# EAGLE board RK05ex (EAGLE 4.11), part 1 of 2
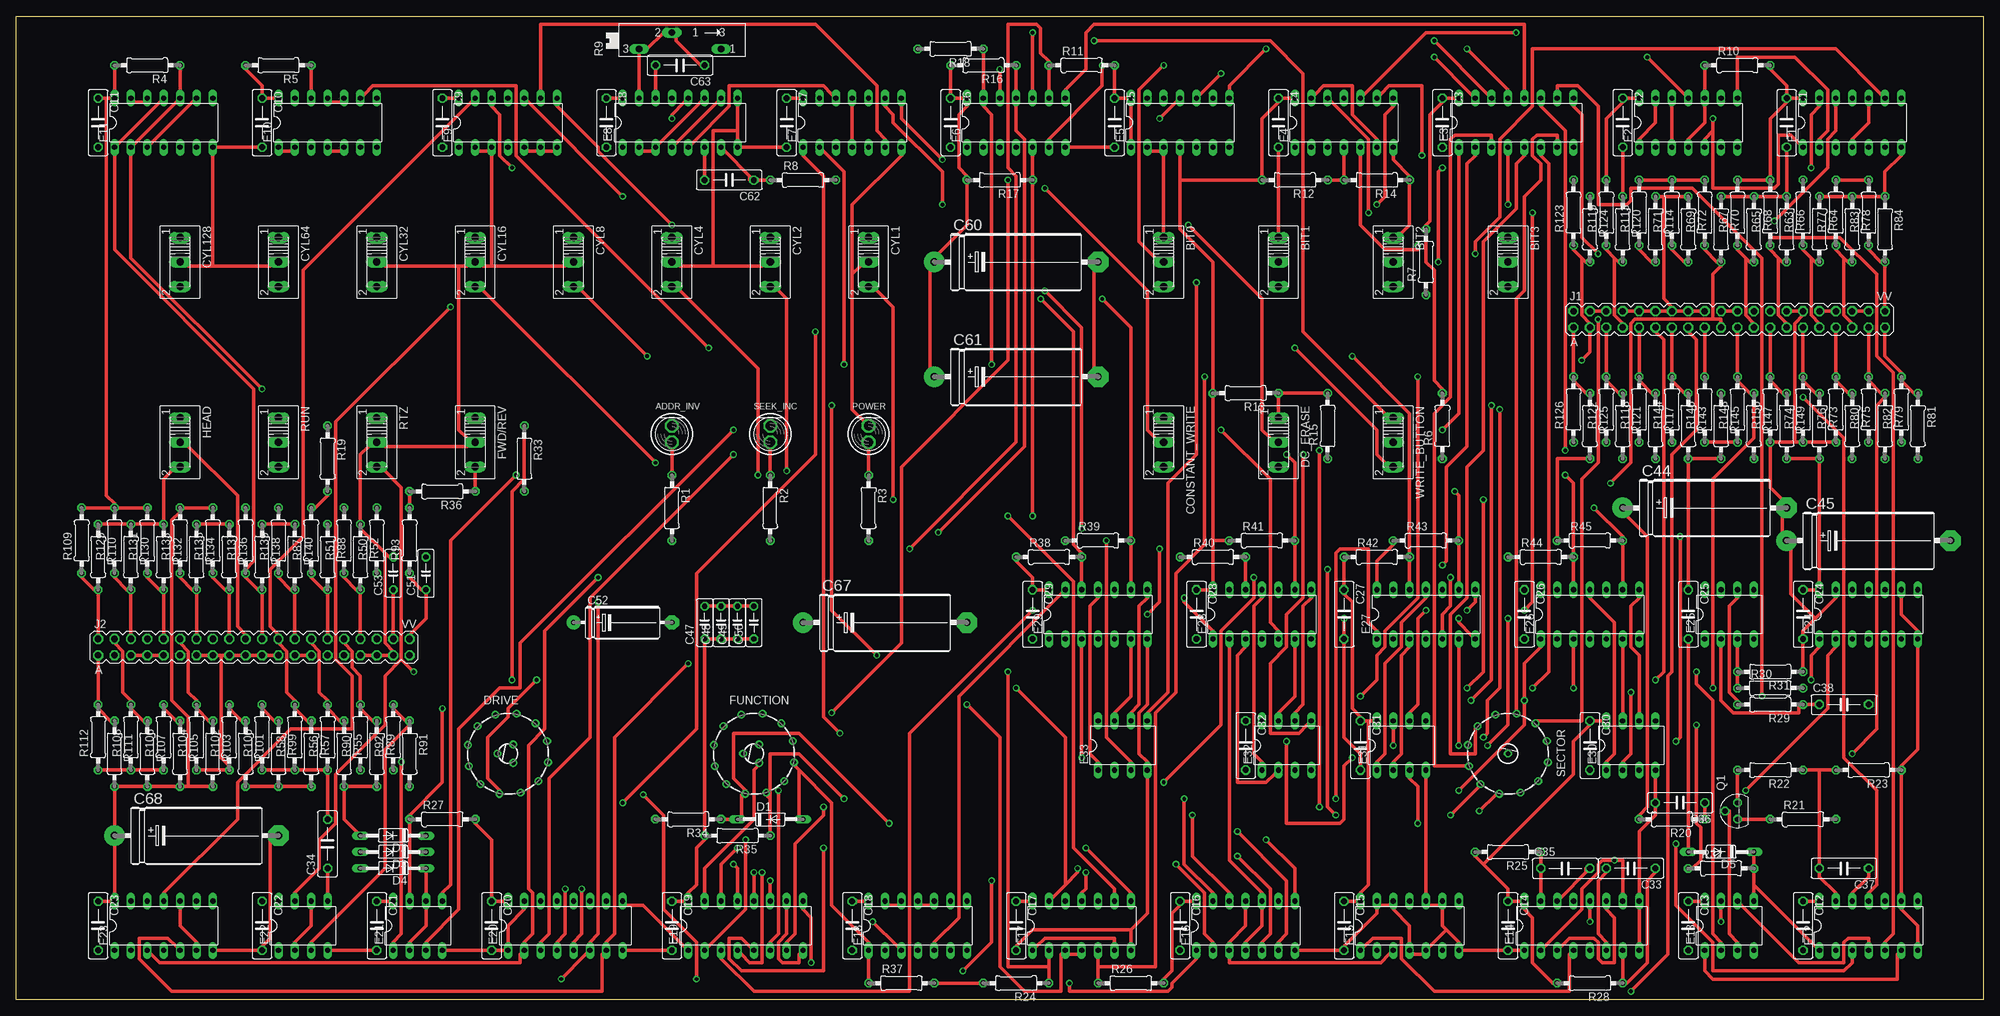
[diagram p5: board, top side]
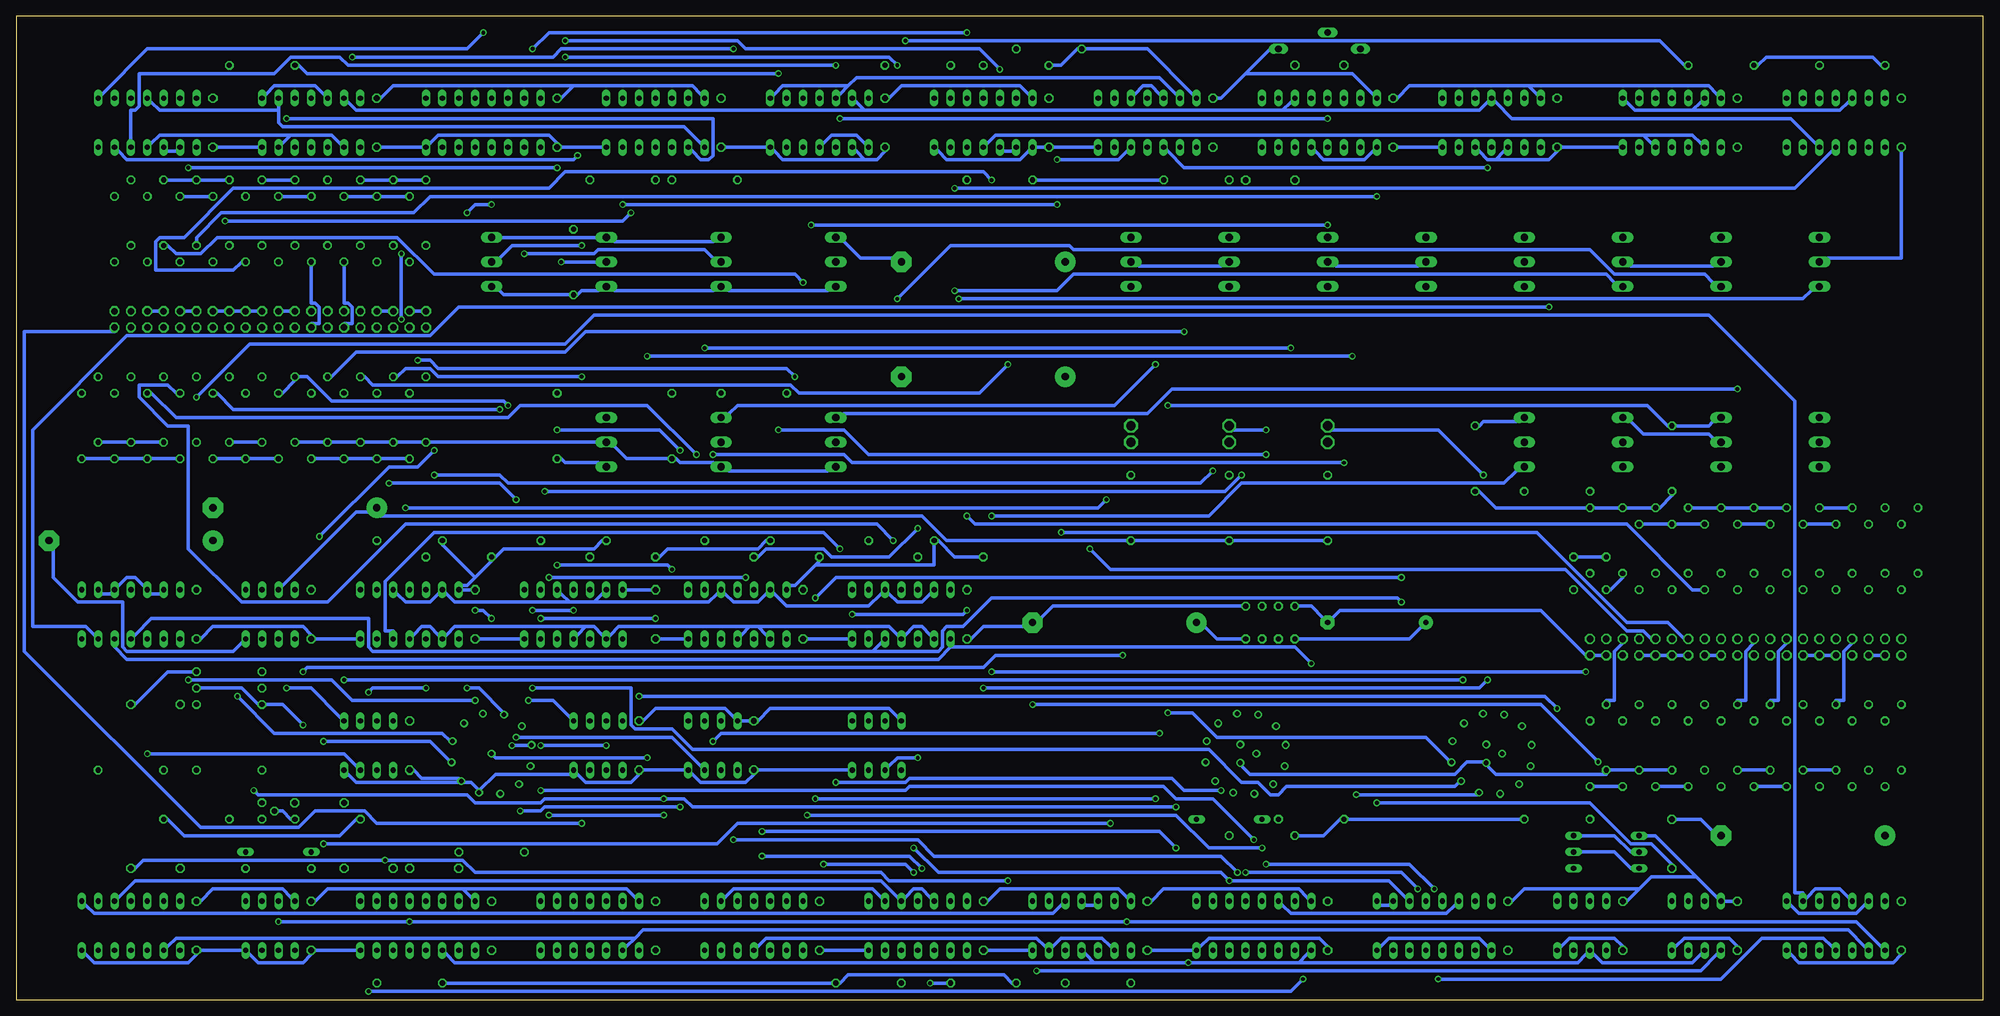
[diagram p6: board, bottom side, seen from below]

Size 304.8 x 152.4 mm. Coordinates in mm from the lower left corner, seen from the top.
Outline: 0,0 0,152.4 304.8,152.4 304.8,0 0,0
Copper layers (1*16): Top 0.035mm / dielectric 1.5mm / Bottom 0.035mm
Design rules "10mils": minimum track width 10mil, minimum drill 24mil, track to track 10mil, track to pad 10mil, pad to pad 10mil, via to via 10mil, smd to smd 10mil, copper to edge 25mil, drill to drill 10mil, minimum pad ring 10mil, minimum via ring 8mil, stop-mask expansion 0mil, vias tented up to drill 0mil, thermal gap 10mil
Net classes: 0 default: width 0.508 mm

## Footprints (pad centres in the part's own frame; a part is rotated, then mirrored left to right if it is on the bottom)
BULB = drill 1.422 octagon: A 0,0; B 0,2.54
255SB = drill 1.118 long: 1 -3.81,0; 2 0,0; 3 3.81,0
C075-032X103 = drill 0.914 octagon: 1 -3.81,0; 2 3.81,0
E25-9 = drill 1.118 pad 3.15 round: + -12.7,0 | drill 1.118 pad 3.15 octagon: - 12.7,0
C050-025X075 = drill 0.813 octagon: 1 -2.54,0; 2 2.54,0
E15-5 = drill 0.813 pad 2.159 round: + -7.62,0 | drill 0.813 pad 2.159 octagon: - 7.62,0
DO35-10 = drill 0.813 long: A 5.08,0; C -5.08,0
DO35Z10 = drill 0.813 long: A 5.08,0; C -5.08,0
50-3POLE30 = drill 0.7 pad 1.2 round: 1 6.207,-1.342; 2 4.704,-4.265; 3 1.941,-6.046; 4 -1.342,-6.207; 5 -4.265,-4.704; 6 -6.046,-1.941; 7 -6.207,1.342; 8 -4.704,4.265; 9 -1.941,6.046; 10 1.342,6.207; 11 4.265,4.704; 12 6.046,1.941; C1 0.825,-1.429; C2 -1.65,0; C3 0.825,1.429
DIL14 = drill 0.813 long: 1 -7.62,-3.81; 2 -5.08,-3.81; 3 -2.54,-3.81; 4 0,-3.81; 5 2.54,-3.81; 6 5.08,-3.81; 7 7.62,-3.81; 8 7.62,3.81; 9 5.08,3.81; 10 2.54,3.81; 11 0,3.81; 12 -2.54,3.81; 13 -5.08,3.81; 14 -7.62,3.81
DIL16 = drill 0.813 long: 1 -8.89,-3.81; 2 -6.35,-3.81; 3 -3.81,-3.81; 4 -1.27,-3.81; 5 1.27,-3.81; 6 3.81,-3.81; 7 6.35,-3.81; 8 8.89,-3.81; 9 8.89,3.81; 10 6.35,3.81; 11 3.81,3.81; 12 1.27,3.81; 13 -1.27,3.81; 14 -3.81,3.81; 15 -6.35,3.81; 16 -8.89,3.81
DIL08 = drill 0.813 long: 1 -3.81,-3.81; 2 -1.27,-3.81; 3 1.27,-3.81; 4 3.81,-3.81; 5 3.81,3.81; 6 1.27,3.81; 7 -1.27,3.81; 8 -3.81,3.81
DEC40PINV = drill 1.016 octagon: A -24.13,-1.27; AA 3.81,-1.27; B -24.13,1.27; BB 3.81,1.27; C -21.59,-1.27; CC 6.35,-1.27; D -21.59,1.27; DD 6.35,1.27; E -19.05,-1.27; EE 8.89,-1.27; F -19.05,1.27; FF 8.89,1.27; H -16.51,-1.27; HH 11.43,-1.27; J -16.51,1.27; JJ 11.43,1.27; K -13.97,-1.27; KK 13.97,-1.27; L -13.97,1.27; LL 13.97,1.27; M -11.43,-1.27; MM 16.51,-1.27; N -11.43,1.27; NN 16.51,1.27; P -8.89,-1.27; PP 19.05,-1.27; R -8.89,1.27; RR 19.05,1.27; S -6.35,-1.27; SS 21.59,-1.27; T -6.35,1.27; TT 21.59,1.27; U -3.81,-1.27; UU 24.13,-1.27; V -3.81,1.27; VV 24.13,1.27; W -1.27,-1.27; X -1.27,1.27; Y 1.27,-1.27; Z 1.27,1.27
TO92E = drill 0.813 octagon: B1 -1.27,0; B2 1.27,0; E 0,1.905
0207/10 = drill 0.813 octagon: 1 -5.08,0; 2 5.08,0
SP19L = drill 1.016 long: A 5.715,-1.27; E -6.985,-1.27; S -1.905,1.27
320-916 = drill 2.007 long: 1 0,4.013; 2 0,0; 3 0,-4.013
M9040P = drill 1.803 long: 1 0,4.699; 2 0,0; 3 0,-4.699
TL3XPO = drill 1.1 pad 1.422 long: 1 -2.54,0; 2 0,0; 3 2.54,0
50-1POLE30 = drill 0.7 pad 1.2 round: 1 6.207,-1.342; 2 4.704,-4.265; 3 1.941,-6.046; 4 -1.342,-6.207; 5 -4.265,-4.704; 6 -6.046,-1.941; 7 -6.207,1.342; 8 -4.704,4.265; 9 -1.941,6.046; 10 1.342,6.207; 11 4.265,4.704; 12 6.046,1.941; C 0,0

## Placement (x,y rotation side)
ADDR_INV  [BULB]  101.6,86.36 0 top
BIT0  [255SB]  177.8,114.3 270 top
BIT1  [255SB]  195.58,114.3 270 top
BIT2  [255SB]  213.36,114.3 270 top
BIT3  [255SB]  231.14,114.3 270 top
C1  .01uf  [C075-032X103]  274.32,135.89 270 top
C2  .01uf  [C075-032X103]  248.92,135.89 270 top
C3  .01uf  [C075-032X103]  220.98,135.89 270 top
C4  .01uf  [C075-032X103]  195.58,135.89 270 top
C5  .01uf  [C075-032X103]  170.18,135.89 270 top
C6  .01uf  [C075-032X103]  144.78,135.89 270 top
C7  .01uf  [C075-032X103]  119.38,135.89 270 top
C8  .01uf  [C075-032X103]  91.44,135.89 270 top
C9  .01uf  [C075-032X103]  66.04,135.89 270 top
C10  .01uf  [C075-032X103]  38.1,135.89 270 top
C11  .01uf  [C075-032X103]  12.7,135.89 270 top
C12  .01uf  [C075-032X103]  276.86,11.43 270 top
C13  .01uf  [C075-032X103]  259.08,11.43 270 top
C14  .01uf  [C075-032X103]  231.14,11.43 270 top
C15  .01uf  [C075-032X103]  205.74,11.43 270 top
C16  .01uf  [C075-032X103]  180.34,11.43 270 top
C17  .01uf  [C075-032X103]  154.94,11.43 270 top
C18  .01uf  [C075-032X103]  129.54,11.43 270 top
C19  .01uf  [C075-032X103]  101.6,11.43 270 top
C20  .01uf  [C075-032X103]  73.66,11.43 270 top
C21  .01uf  [C075-032X103]  55.88,11.43 270 top
C22  .01uf  [C075-032X103]  38.1,11.43 270 top
C23  .01uf  [C075-032X103]  12.7,11.43 270 top
C24  .01uf  [C075-032X103]  276.86,59.69 270 top
C25  .01uf  [C075-032X103]  259.08,59.69 270 top
C26  .01uf  [C075-032X103]  233.68,59.69 270 top
C27  .01uf  [C075-032X103]  205.74,59.69 270 top
C28  .01uf  [C075-032X103]  182.88,59.69 270 top
C29  .01uf  [C075-032X103]  157.48,59.69 270 top
C30  .01uf  [C075-032X103]  243.84,39.37 270 top
C31  .01uf  [C075-032X103]  208.28,39.37 270 top
C32  .01uf  [C075-032X103]  190.5,39.37 270 top
C33  470pf  [C075-032X103]  250.19,20.32 180 top
C34  .001uf  [C075-032X103]  48.26,24.13 90 top
C35  470pf  [C075-032X103]  240.03,20.32 0 top
C36  .033uf  [C075-032X103]  257.81,30.48 180 top
C37  .001uf  [C075-032X103]  283.21,20.32 180 top
C38  100pf  [C075-032X103]  283.21,45.72 0 top
C44  6.8uf  [E25-9]  261.62,76.2 0 top
C45  6.8uf  [E25-9]  287.02,71.12 0 top
C47  .22uf  [C050-025X075]  106.68,58.42 90 top
C48  .22uf  [C050-025X075]  109.22,58.42 90 top
C49  .22uf  [C050-025X075]  111.76,58.42 90 top
C50  .22uf  [C050-025X075]  114.3,58.42 90 top
C51  .001  [C050-025X075]  63.5,66.04 90 top
C52  39uf  [E15-5]  93.98,58.42 0 top
C53  .001  [C050-025X075]  58.42,66.04 90 top
C60  6.8uf  [E25-9]  154.94,114.3 0 top
C61  6.8uf  [E25-9]  154.94,96.52 0 top
C62  27pf  [C075-032X103]  110.49,127 180 top
C63  47pf  [C075-032X103]  102.87,144.78 180 top
C67  6.8uf  [E25-9]  134.62,58.42 0 top
C68  6.8uf  [E25-9]  27.94,25.4 0 top
CONSTANT_WRITE  [255SB]  177.8,86.36 270 top
CYL1  [255SB]  132.08,114.3 270 top
CYL2  [255SB]  116.84,114.3 270 top
CYL4  [255SB]  101.6,114.3 270 top
CYL8  [255SB]  86.36,114.3 270 top
CYL16  [255SB]  71.12,114.3 270 top
CYL32  [255SB]  55.88,114.3 270 top
CYL64  [255SB]  40.64,114.3 270 top
CYL128  [255SB]  25.4,114.3 270 top
D1  D664  [DO35-10]  116.84,27.94 0 top
D2  D664  [DO35-10]  58.42,25.4 180 top
D3  D664  [DO35-10]  58.42,22.86 180 top
D4  D664  [DO35-10]  58.42,20.32 180 top
D5  1N746  [DO35Z10]  264.16,22.86 180 top
DC_ERASE  [255SB]  195.58,86.36 270 top
DRIVE  50-3POLE30  [50-3POLE30]  76.2,38.1 0 top
E1  74LS10N  [DIL14]  284.48,135.89 0 top
E2  74LS74N  [DIL14]  259.08,135.89 0 top
E3  74LS42N  [DIL16]  232.41,135.89 0 top
E4  [DIL14]  205.74,135.89 0 top
E5  74LS74N  [DIL14]  180.34,135.89 0 top
E6  74LS04N  [DIL14]  154.94,135.89 0 top
E7  74LS00N  [DIL14]  129.54,135.89 0 top
E8  74LS123N  [DIL16]  102.87,135.89 0 top
E9  DS8881N  [DIL14]  76.2,135.89 0 top
E10  74LS00N  [DIL14]  48.26,135.89 0 top
E11  74LS74N  [DIL14]  22.86,135.89 0 top
E12  74LS04N  [DIL14]  287.02,11.43 0 top
E13  DS75451N  [DIL08]  265.43,11.43 0 top
E14  74HCT123N  [DIL16]  242.57,11.43 0 top
E15  74LS00N  [DIL14]  215.9,11.43 0 top
E16  74LS10N  [DIL14]  190.5,11.43 0 top
E17  74LS00N  [DIL14]  165.1,11.43 0 top
E18  74LS74N  [DIL14]  139.7,11.43 0 top
E19  74LS193N  [DIL16]  113.03,11.43 0 top
E20  74LS193N  [DIL16]  85.09,11.43 0 top
E21  DS75451N  [DIL08]  62.23,11.43 0 top
E22  DS75451N  [DIL08]  44.45,11.43 0 top
E23  74LS10N  [DIL14]  22.86,11.43 0 top
E24  74LS20N  [DIL14]  287.02,59.69 0 top
E25  LM741P  [DIL08]  265.43,59.69 0 top
E26  74LS00N  [DIL14]  243.84,59.69 0 top
E27  74LS00N  [DIL14]  218.44,59.69 0 top
E28  74LS00N  [DIL14]  193.04,59.69 0 top
E29  74LS00N  [DIL14]  167.64,59.69 0 top
E30  DS75451N  [DIL08]  250.19,39.37 0 top
E31  DS75451N  [DIL08]  214.63,39.37 0 top
E32  DS75451N  [DIL08]  196.85,39.37 0 top
E33  DS75451N  [DIL08]  171.45,39.37 0 top
FUNCTION  50-3POLE30  [50-3POLE30]  114.3,38.1 0 top
FWD/REV  [255SB]  71.12,86.36 270 top
HEAD  [255SB]  25.4,86.36 270 top
J1  DEC40PINSV  [DEC40PINV]  265.43,105.41 0 top
J2  DEC40PINSV  [DEC40PINV]  36.83,54.61 0 top
POWER  [BULB]  132.08,86.36 0 top
Q1  2N4894  [TO92E]  266.7,29.21 90 top
R1  0ohm  [0207/10]  101.6,76.2 270 top
R2  0ohm  [0207/10]  116.84,76.2 270 top
R3  0ohm  [0207/10]  132.08,76.2 270 top
R4  1K  [0207/10]  20.32,144.78 180 top
R5  56K  [0207/10]  40.64,144.78 180 top
R6  56K  [0207/10]  220.98,88.9 90 top
R7  1K  [0207/10]  218.44,114.3 90 top
R8  5.6k*  [0207/10]  121.92,127 0 top
R9  10K*  [SP19L]  103.5,148.59 0 top
R10  1K  [0207/10]  266.7,144.78 0 top
R11  1K  [0207/10]  165.1,144.78 0 top
R12  330  [0207/10]  198.12,127 180 top
R13  330  [0207/10]  190.5,93.98 180 top
R14  750  [0207/10]  210.82,127 180 top
R15  750  [0207/10]  203.2,88.9 90 top
R16  1K  [0207/10]  149.86,144.78 180 top
R17  1K  [0207/10]  152.4,127 180 top
R18  1K  [0207/10]  144.78,147.32 180 top
R19  1K  [0207/10]  48.26,83.82 270 top
R20  470K  [0207/10]  256.54,27.94 180 top
R21  330  [0207/10]  276.86,27.94 0 top
R22  120  [0207/10]  271.78,35.56 180 top
R23  68  [0207/10]  287.02,35.56 180 top
R24  1K  [0207/10]  154.94,2.54 180 top
R25  10K  [0207/10]  231.14,22.86 180 top
R26  1K  [0207/10]  172.72,2.54 0 top
R27  1K  [0207/10]  66.04,27.94 0 top
R28  22K  [0207/10]  243.84,2.54 180 top
R29  100K  [0207/10]  271.78,45.72 180 top
R30  100K  [0207/10]  271.78,48.26 0 top
R31  1M  [0207/10]  271.78,50.8 180 top
R32  1K  [0207/10]  264.16,20.32 0 top
R33  1K  [0207/10]  78.74,83.82 270 top
R34  1K  [0207/10]  104.14,27.94 180 top
R35  1K  [0207/10]  111.76,25.4 180 top
R36  1K  [0207/10]  66.04,78.74 180 top
R37  1K  [0207/10]  137.16,2.54 0 top
R38  1K  [0207/10]  160.02,68.58 0 top
R39  1K  [0207/10]  167.64,71.12 0 top
R40  1K  [0207/10]  185.42,68.58 0 top
R41  1K  [0207/10]  193.04,71.12 0 top
R42  1K  [0207/10]  210.82,68.58 0 top
R43  1K  [0207/10]  218.44,71.12 0 top
R44  1K  [0207/10]  236.22,68.58 0 top
R45  1K  [0207/10]  243.84,71.12 0 top
R50  120  [0207/10]  55.88,71.12 90 top
R51  120  [0207/10]  50.8,71.12 90 top
R52  120  [0207/10]  53.34,68.58 270 top
R55  120  [0207/10]  50.8,38.1 270 top
R56  120  [0207/10]  48.26,40.64 90 top
R57  120  [0207/10]  45.72,38.1 270 top
R58  120  [0207/10]  43.18,40.64 90 top
R63  120  [0207/10]  276.86,121.92 90 top
R64  120  [0207/10]  279.4,119.38 270 top
R65  120  [0207/10]  271.78,121.92 90 top
R66  120  [0207/10]  274.32,119.38 270 top
R67  120  [0207/10]  266.7,121.92 90 top
R68  120  [0207/10]  269.24,119.38 270 top
R69  120  [0207/10]  261.62,121.92 90 top
R70  120  [0207/10]  264.16,119.38 270 top
R71  120  [0207/10]  256.54,121.92 90 top
R72  120  [0207/10]  259.08,119.38 270 top
R73  120  [0207/10]  279.4,88.9 270 top
R74  120  [0207/10]  276.86,91.44 90 top
R75  120  [0207/10]  284.48,88.9 270 top
R76  120  [0207/10]  281.94,91.44 90 top
R77  120  [0207/10]  281.94,121.92 90 top
R78  120  [0207/10]  284.48,119.38 270 top
R79  120  [0207/10]  289.56,88.9 270 top
R80  120  [0207/10]  287.02,91.44 90 top
R81  120  [0207/10]  294.64,88.9 270 top
R82  120  [0207/10]  292.1,91.44 90 top
R83  120  [0207/10]  287.02,121.92 90 top
R84  120  [0207/10]  289.56,119.38 270 top
R87  120  [0207/10]  45.72,71.12 90 top
R88  120  [0207/10]  48.26,68.58 270 top
R89  120  [0207/10]  55.88,38.1 270 top
R90  120  [0207/10]  53.34,40.64 90 top
R91  120  [0207/10]  60.96,38.1 270 top
R92  120  [0207/10]  58.42,40.64 90 top
R93  120  [0207/10]  60.96,71.12 90 top
R99  120  [0207/10]  40.64,38.1 270 top
R100  120  [0207/10]  38.1,40.64 90 top
R101  120  [0207/10]  35.56,38.1 270 top
R102  120  [0207/10]  33.02,40.64 90 top
R103  120  [0207/10]  30.48,38.1 270 top
R104  120  [0207/10]  27.94,40.64 90 top
R105  120  [0207/10]  25.4,38.1 270 top
R106  120  [0207/10]  22.86,40.64 90 top
R107  120  [0207/10]  20.32,38.1 270 top
R108  120  [0207/10]  17.78,40.64 90 top
R109  120  [0207/10]  10.16,71.12 90 top
R110  120  [0207/10]  12.7,68.58 270 top
R111  120  [0207/10]  15.24,38.1 270 top
R112  120  [0207/10]  12.7,40.64 90 top
R113  120  [0207/10]  251.46,121.92 90 top
R114  120  [0207/10]  254,119.38 270 top
R117  120  [0207/10]  254,88.9 270 top
R118  120  [0207/10]  251.46,91.44 90 top
R119  120  [0207/10]  246.38,121.92 90 top
R120  120  [0207/10]  248.92,119.38 270 top
R121  120  [0207/10]  248.92,88.9 270 top
R122  120  [0207/10]  246.38,91.44 90 top
R123  120  [0207/10]  241.3,121.92 90 top
R124  120  [0207/10]  243.84,119.38 270 top
R125  120  [0207/10]  243.84,88.9 270 top
R126  120  [0207/10]  241.3,91.44 90 top
R129  120  [0207/10]  15.24,71.12 90 top
R130  120  [0207/10]  17.78,68.58 270 top
R131  120  [0207/10]  20.32,71.12 90 top
R132  120  [0207/10]  22.86,68.58 270 top
R133  120  [0207/10]  25.4,71.12 90 top
R134  120  [0207/10]  27.94,68.58 270 top
R135  120  [0207/10]  30.48,71.12 90 top
R136  120  [0207/10]  33.02,68.58 270 top
R137  120  [0207/10]  35.56,71.12 90 top
R138  120  [0207/10]  38.1,68.58 270 top
R139  120  [0207/10]  40.64,71.12 90 top
R140  120  [0207/10]  43.18,68.58 270 top
R143  120  [0207/10]  259.08,88.9 270 top
R144  120  [0207/10]  256.54,91.44 90 top
R145  120  [0207/10]  264.16,88.9 270 top
R146  120  [0207/10]  261.62,91.44 90 top
R147  120  [0207/10]  269.24,88.9 270 top
R148  120  [0207/10]  266.7,91.44 90 top
R149  120  [0207/10]  274.32,88.9 270 top
R150  120  [0207/10]  271.78,91.44 90 top
RTZ  [255SB]  55.88,86.36 270 top
RUN  [255SB]  40.64,86.36 270 top
S1  [320-916]  not placed on the board
S2  [M9040P]  not placed on the board
S3  TL32PO  [TL3XPO]  not placed on the board
S4  TL36PO  [TL3XPO]  not placed on the board
SECTOR  50-1POLE30  [50-1POLE30]  231.14,38.1 270 top
SEEK_INC  [BULB]  116.84,86.36 0 top
WRITE_BUTTON  MOM  [255SB]  213.36,86.36 270 top

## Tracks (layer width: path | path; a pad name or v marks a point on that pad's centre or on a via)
0BIT  (via drill 0.61)
  Top 0.508: v217.81,130.81 217.81,141.6 212.72,141.6 211.46,140.34 E4.9
  Bottom 0.508: v217.81,130.81 218.44,130.18 287.65,130.18 288.93,131.44 E1.6
1.44MHZ  (via drill 0.61)
  Top 0.508: v101.6,136.53 101.6,137.16 103.5,139.06 E8.12 | v177.16,136.53 179.71,139.06 E5.11
  Bottom 0.508: v177.16,136.53 v101.6,136.53
1BIT  (via drill 0.61)
  Top 0.508: v232.41,149.86 218.44,149.86 208.91,140.34 E4.10
  Bottom 0.508: v232.41,149.86 234.95,147.32 284.48,147.32 291.46,140.34 E1.8
1L  (via drill 0.61)
  Top 0.508: v252.73,146.05 258.44,140.34 E2.11 | v193.68,147.32 187.96,141.6 187.96,140.97 E5.8
  Bottom 0.508: 175.9,141.6 177.16,140.34 E5.12 | 175.9,141.6 174.62,142.88 127.64,142.88 125.09,140.34 E7.13 | 175.9,141.6 186.06,141.6 187.32,140.34 E5.8 | v252.73,146.05 221.62,146.05 220.34,147.32 v193.68,147.32
2.88MHZ
  Top 0.508: E8.4 102.23,132.72 108.58,139.06 E8.10
2BIT  (via drill 0.61)
  Top 0.508: v209.55,121.92 209.55,133.35 203.84,139.06 E4.12 | v272.42,120.65 280.67,128.91 280.67,133.35 281.94,134.62 281.94,138.43 E1.12
  Bottom 0.508: v209.55,121.92 210.82,120.65 v272.42,120.65
2H
  Bottom 0.508: 264.16,137.79 264.16,138.43 E2.9 | 264.16,137.79 264.16,135.89 263.52,135.25 201.29,135.25 198.75,132.72 E4.1 | 264.16,137.79 282.57,137.79 283.85,139.06 E1.11
2L
  Top 0.508: E2.3 256.54,133.35 256.54,138.43 E2.12 | E1.2 279.4,133.35 280.67,134.62 280.67,140.97 275.59,146.05 266.7,146.05 266.7,140.97 E2.8
  Bottom 0.508: E1.2 280.04,131.44 281.31,131.44 E1.3 | E2.8 266.06,140.34 264.8,141.6 258.44,141.6 257.18,140.34 E2.12
3BIT
  Top 0.508: E4.13 201.29,140.34 202.56,141.6 207.01,141.6 207.01,137.16 210.82,133.35 E4.6
4H  (via drill 0.61)
  Top 0.508: v262.89,136.53 262.89,134.62 | 262.89,134.62 261.62,133.35 E2.5 | 262.89,134.62 262.89,125.73 272.42,125.73 273.05,126.36 273.05,133.99 274.95,133.99 276.23,132.72 E1.1
  Bottom 0.508: v262.89,136.53 196.85,136.53 196.85,130.81 197.49,130.18 198.75,130.18 200.03,131.44 E4.2
4L
  Top 0.508: E1.4 284.48,133.35 287.02,135.89 287.02,138.43 E1.10
  Bottom 0.508: 262.25,133.99 255.91,133.99 254.63,132.72 E2.2 | 262.25,133.99 263.52,132.72 E2.6 | 262.25,133.99 282.57,133.99 283.85,132.72 E1.4
202_DETECT_L  (via drill 0.61)
  Top 0.508: v67.31,107.31 49.53,89.53 49.53,52.7 52.07,50.16 52.07,41.91 42.55,41.91 34.29,33.66 34.29,27.94 22.86,16.51 E23.11
  Bottom 0.508: v67.31,107.31 236.22,107.31 240.66,102.87 287.65,102.87 302.26,88.27 302.26,57.78 294,57.78 292.74,56.52 E24.6
+3V  (via drill 0.61)
  Top 0.508: E22.2 43.18,8.89 45.72,11.43 45.72,13.97 E22.6 | E21.2 60.96,8.89 63.5,11.43 63.5,13.97 E21.6 63.5,16.51 63.5,19.68 D4.C | E14.3 239.4,8.26 240.66,9.53 244.47,9.53 245.11,8.89 245.11,6.35 245.75,5.71 247.65,5.71 247.65,12.7 246.38,13.97 E14.11 | E19.1 103.5,8.26 97.16,14.61 94.61,14.61 E20.9 | v123.19,5.71 123.19,12.7 121.92,13.97 E19.9
  Bottom 0.508: E22.2 43.81,6.99 45.09,5.71 59.05,5.71 60.33,6.99 E21.2 61.59,6.99 62.87,5.71 106.05,5.71 | 137.79,5.71 139.06,6.99 E18.4 | 106.05,5.71 v123.19,5.71 137.79,5.71 | 106.05,5.71 104.78,6.99 E19.1 | E20.10 92.08,14.61 93.34,14.61 E20.9 | 137.79,5.71 236.85,5.71 238.12,6.99 E14.3
+3VA  (via drill 0.61)
  Top 0.508: v128.27,98.42 128.27,128.27 125.09,131.44 E7.2 | DC_ERASE.1 195.58,90.81 195.58,93.34 R13.1 196.22,93.98 202.56,93.98 R15.2
  Bottom 0.508: v128.27,98.42 134.62,92.08 193.04,92.08 194.31,90.81 DC_ERASE.1
+3VB
  Top 0.508: R12.1 203.84,127 205.1,127 R14.2 205.74,127.64 205.74,130.81 E4.4
+3VC  (via drill 0.61)
  Top 0.508: R4.1 25.4,144.15 25.4,140.97 E11.10 24.77,139.06 18.41,132.72 E11.2 17.78,130.81 17.78,114.94 v38.1,94.61
  Bottom 0.508: v38.1,94.61 125.73,94.61 129.54,90.81 176.53,90.81 CONSTANT_WRITE.1
+15V
  Top 0.508: R20.2 251.46,28.57 252.73,29.84 252.73,71.75 249.56,74.93 C44.+
  Bottom 0.508: R20.2 252.09,27.94 254.63,25.4 278.76,25.4 281.31,27.94 R21.2 | R1.2 102.23,71.12 116.2,71.12 R2.2 117.47,71.12 131.44,71.12 R3.2 132.72,71.12 160.66,71.12 164.47,74.93 248.28,74.93 C44.+ 250.19,75.56 252.09,75.56 263.52,64.14 E25.7
-15V
  Bottom 0.508: E25.4 269.88,55.24 271.14,53.98 287.65,53.98 288.29,54.61 288.29,61.59 295.27,61.59 299.08,65.41 299.08,69.85 C45.-
ADDR_COUNTER_1  (via drill 0.61)
  Top 0.508: v157.48,60.33 138.43,41.27 138.43,1.27 114.3,1.27 109.22,6.35 E19.3 | v175.26,59.69 177.16,61.59 v177.16,69.85
  Bottom 0.508: v157.48,60.33 158.12,59.69 v175.26,59.69 | v177.16,69.85 179.71,72.39 240.03,72.39 247.65,64.77 247.65,57.15 246.38,57.15 E26.5
ADDR_COUNTER_2  (via drill 0.61)
  Top 0.508: v113.03,24.77 113.03,13.97 107.31,8.26 E19.2 | v223.52,32.38 233.68,42.55 v233.68,46.35 233.68,52.07 236.22,54.61 E26.1 | v278.13,49.53 278.13,53.34 279.4,54.61 E24.1
  Bottom 0.508: v113.03,24.77 119.38,31.11 125.09,31.11 127,33.02 166.37,33.02 167,32.38 v223.52,32.38 | v278.13,49.53 255.91,49.53 252.73,46.35 v233.68,46.35
ADDR_COUNTER_4  (via drill 0.61)
  Top 0.508: v118.11,32.38 118.11,10.16 116.84,8.89 E19.6 | v177.8,33.66 186.69,42.55 186.69,57.15 191.77,62.23 v191.77,65.41 | v222.25,65.41 222.25,60.96 220.98,59.69 220.98,57.15 E27.5
  Bottom 0.508: v118.11,32.38 123.83,32.38 125.73,34.29 166.37,34.29 167,33.66 v177.8,33.66 | v191.77,65.41 v222.25,65.41
ADDR_COUNTER_8  (via drill 0.61)
  Top 0.508: v125.09,29.84 125.09,28.57 120.65,24.13 120.65,10.16 119.38,8.89 E19.7 | v204.47,31.11 204.47,69.22 205.1,69.85 209.55,69.85 209.55,58.42 210.82,57.15 E27.1 | v267.97,32.38 280.67,45.09 280.67,53.34 281.94,54.61 E24.2
  Bottom 0.508: v125.09,29.84 200.03,29.84 201.29,31.11 v204.47,31.11 222.88,31.11 223.52,30.48 233.68,30.48 234.95,31.75 267.33,31.75 v267.97,32.38
ADDR_COUNTER_16  (via drill 0.61)
  Top 0.508: v111.12,84.45 88.9,62.23 88.9,40.64 82.55,34.29 82.55,10.16 81.28,8.89 E20.3 | v186.69,88.27 194.31,80.64 194.31,58.42 195.58,57.15 E28.5
  Bottom 0.508: v111.12,84.45 172.72,84.45 176.53,88.27 v186.69,88.27
ADDR_COUNTER_32  (via drill 0.61)
  Top 0.508: E23.3 20.95,6.99 22.23,5.71 78.11,5.71 78.11,6.99 E20.2 78.74,8.89 80.01,10.16 80.01,16.51 79.38,17.14 79.38,39.37 81.92,41.91 81.92,57.15 v90.17,65.41 | v180.97,62.23 180.97,61.59 185.42,57.15 E28.1
  Bottom 0.508: v180.97,62.23 177.8,65.41 v90.17,65.41
ADDR_COUNTER_64  (via drill 0.61)
  Top 0.508: v84.45,3.17 88.27,6.99 E20.6 88.9,8.89 90.17,10.16 v90.17,61.59
  Bottom 0.508: v84.45,3.17 40.64,3.17 34.29,9.53 24.77,9.53 23.5,8.26 E23.4 | 172.09,53.98 170.81,55.24 E29.5 | 172.09,53.98 249.56,53.98 250.19,54.61 250.19,59.05 283.85,59.05 286.38,56.52 E24.4 | v90.17,61.59 90.81,62.23 153.67,62.23 158.12,57.78 160.66,57.78 161.29,57.15 161.29,54.61 161.93,53.98 172.09,53.98
ADDR_COUNTER_128  (via drill 0.61)
  Top 0.508: E23.5 24.77,8.26 23.5,9.53 19.05,9.53 19.05,6.35 24.13,1.27 90.81,1.27 90.81,6.99 E20.7 91.44,8.89 92.71,10.16 92.71,40.64 v104.14,52.07
  Bottom 0.508: 160.02,54.61 161.93,52.7 287.65,52.7 289.56,54.61 E24.5 | 160.02,54.61 E29.1 160.02,54.61 | v104.14,52.07 106.68,54.61 160.02,54.61
ADDR_SOURCE_H
  Top 0.508: E18.5 142.24,8.89 146.05,12.7 146.05,46.99 161.93,62.87 E29.13
  Bottom 0.508: E26.10 245.75,62.87 244.47,61.59 240.66,61.59 239.4,62.87 E26.13 238.12,62.87 236.85,61.59 219.07,61.59 | 215.26,61.59 214,62.87 E27.13 | 215.26,61.59 219.07,61.59 | 219.07,61.59 220.34,62.87 E27.10 | 215.26,61.59 197.49,61.59 196.22,62.87 E28.10 194.94,62.87 193.68,61.59 189.87,61.59 188.59,62.87 E28.13 187.32,62.87 185.42,60.96 172.72,60.96 170.81,62.87 E29.10 169.54,62.87 168.28,61.59 164.47,61.59 163.19,62.87 E29.13
ADDR_SOURCE_L
  Top 0.508: E16.4 190.5,8.89 193.04,11.43 193.04,13.97 E16.10 193.04,16.51 187.96,21.59 187.96,54.61 E28.2
  Bottom 0.508: E18.2 135.25,8.26 136.53,9.53 142.88,9.53 144.15,8.26 E18.6 145.41,8.26 146.69,9.53 188.59,9.53 189.87,8.26 E16.4 | E26.4 243.21,56.52 241.94,57.78 240.66,57.78 239.4,56.52 E26.2 238.12,56.52 236.85,57.78 216.53,57.78 | 216.53,57.78 215.26,57.78 214,56.52 E27.2 212.72,56.52 211.46,57.78 191.13,57.78 | 216.53,57.78 217.81,56.52 E27.4 | E29.2 163.19,56.52 164.47,57.78 165.74,57.78 167,56.52 E29.4 168.28,56.52 169.54,57.78 189.87,57.78 | 189.87,57.78 188.59,56.52 E28.2 | 191.13,57.78 189.87,57.78 | 191.13,57.78 192.41,56.52 E28.4
ADDRESS_INVALID_L  (via drill 0.61)
  Top 0.508: v77.47,81.28 67.31,71.12 67.31,17.78 66.04,16.51 E21.5
  Bottom 0.508: v77.47,81.28 84.45,88.27 100.97,88.27 ADDR_INV.B
BIT_0L  (via drill 0.61)
  Top 0.508: v177.8,144.78 173.99,140.97 173.99,117.47 176.53,114.94 BIT0.2
  Bottom 0.508: v177.8,144.78 253.37,144.78 254.63,146.05 262.25,146.05 264.8,143.51 285.75,143.51 285.75,138.43 286.38,137.79 287.02,137.79 287.02,133.35 E1.5
BIT_1L  (via drill 0.61)
  Top 0.508: v226.06,115.57 226.06,117.47 229.87,121.28 229.87,133.35 234.95,138.43 234.95,147.32 281.94,147.32 288.93,140.34 E1.9
  Bottom 0.508: v226.06,115.57 215.26,115.57 214.63,116.2 198.12,116.2 196.85,114.94 BIT1.2
BIT_2L  (via drill 0.61)
  Top 0.508: v278.13,128.91 278.13,137.16 279.4,138.43 E1.13 | v220.98,128.91 220.34,128.27 v220.34,114.3
  Bottom 0.508: v220.98,128.91 v278.13,128.91 | v220.34,114.3 214.63,114.3 BIT2.2
BIT_3L  (via drill 0.61)
  Top 0.508: v217.17,116.84 217.17,116.2 212.09,116.2 208.28,120.02 208.28,130.81 E4.5
  Bottom 0.508: v217.17,116.84 227.97,116.84 229.87,114.94 BIT3.2
BUS_ADDR_ACCEPTED_L
  Top 0.508: 247.65,114.94 248.28,114.3 R120.2 | 247.65,114.94 246.38,116.2 R119.1 | 247.65,114.94 247.65,106.05 248.92,104.78 J1.H
BUS_ADDRESS_INVALID_L  (via drill 0.61)
  Top 0.508: 167.64,5.08 167.64,6.35 E17.5 | 167.64,5.08 167.64,3.17 R26.1 | 242.57,114.94 241.3,116.2 R123.1 | 242.57,114.94 243.21,114.3 R124.2 | 242.57,114.94 242.57,106.05 243.84,104.78 J1.C 243.84,103.5 243.84,100.33 v242.57,99.06 | 167.64,5.08 176.53,5.08 176.53,44.45 179.71,47.62 179.71,66.04 184.15,70.48 v184.15,96.52
  Bottom 0.508: v184.15,96.52 185.42,97.79 239.4,97.79 240.66,99.06 v242.57,99.06
BUS_CA_00_L  (via drill 0.61)
  Top 0.508: v262.89,48.26 262.89,80.64 269.24,87 269.24,93.34 R147.1 268.61,93.98 266.7,95.89 R148.2 266.7,97.16 266.7,103.5 J1.Y
  Bottom 0.508: v262.89,48.26 259.08,48.26 254.63,43.81 E30.5
BUS_CA_01_L  (via drill 0.61)
  Top 0.508: v284.48,38.1 288.29,41.91 288.29,92.08 289.56,93.34 R79.1 288.93,93.98 287.02,95.89 R80.2 287.02,97.16 287.02,103.5 J1.SS
  Bottom 0.508: v284.48,38.1 254,38.1 252.09,36.2 E30.3
BUS_CA_02_L  (via drill 0.61)
  Top 0.508: v225.43,46.35 228.6,49.53 v228.6,92.08 | J1.U 261.62,103.5 261.62,97.16 R146.2
  Bottom 0.508: v225.43,46.35 221.62,46.35 219.07,43.81 E31.5 | v228.6,92.08 229.24,92.71 255.91,92.71 259.71,96.52 260.99,96.52 R146.2 261.62,95.89 263.52,93.98 R145.1
BUS_CA_03_L  (via drill 0.61)
  Top 0.508: R81.1 294,93.98 292.1,95.89 R82.2 292.1,97.16 289.56,99.69 289.56,103.5 J1.UU | v217.17,27.3 217.17,33.02 215.9,34.29 E31.3
  Bottom 0.508: v217.17,27.3 248.92,27.3 250.82,29.21 258.44,29.21 260.99,26.67 276.23,26.67 303.53,53.98 303.53,103.5 289.56,103.5 J1.UU
BUS_CA_04_L  (via drill 0.61)
  Top 0.508: v199.39,84.45 199.39,62.23 196.85,59.69 196.85,54.61 194.31,52.07 194.31,41.27 198.75,41.27 200.03,42.55 E32.5 | R75.1 283.85,93.98 281.94,95.89 R76.2 281.94,97.16 281.94,103.5 J1.MM
  Bottom 0.508: v199.39,84.45 207.01,92.08 226.69,92.08 228.6,90.17 280.04,90.17 283.85,93.98 R75.1
BUS_CA_05_L  (via drill 0.61)
  Top 0.508: v227.33,40.64 227.97,41.27 227.97,46.35 229.87,48.26 v229.87,91.44 | R149.1 273.69,93.98 271.78,95.89 R150.2 271.78,97.16 271.78,103.5 J1.CC
  Bottom 0.508: v227.33,40.64 203.2,40.64 198.75,36.2 E32.3 | v229.87,91.44 271.14,91.44 273.69,93.98 R149.1
BUS_CA_06_L  (via drill 0.61)
  Top 0.508: v182.88,111.12 182.88,84.45 178.44,80.01 178.44,47.62 175.26,44.45 E33.5 | 283.21,114.94 281.94,116.2 R77.1 | 283.21,114.94 283.85,114.3 R78.2 | 283.21,114.94 283.21,106.05 284.48,104.78 J1.PP
  Bottom 0.508: v182.88,111.12 184.15,112.39 240.03,112.39 245.75,118.11 273.69,118.11 276.23,115.57 280.04,115.57 281.31,116.84 R77.1
BUS_CA_07_L  (via drill 0.61)
  Top 0.508: v168.91,71.12 168.91,40.64 172.72,36.83 E33.3 | R73.1 278.76,93.98 276.86,95.89 R74.2 276.86,97.16 276.86,103.5 J1.HH
  Bottom 0.508: v168.91,71.12 171.45,73.66 244.47,73.66 256.54,61.59 269.88,61.59 278.13,69.85 278.13,88.9 281.31,88.9 285.75,93.34 285.75,95.25 281.31,95.25 280.04,93.98 R73.1
BUS_DATA&CLOCK_L  (via drill 0.61)
  Top 0.508: 278.13,114.94 276.86,116.2 R63.1 | 278.13,114.94 278.76,114.3 R64.2 | v93.98,124.46 79.38,139.06 E9.10 | 278.13,114.94 278.13,106.05 279.4,104.78 J1.KK
  Bottom 0.508: v93.98,124.46 240.66,124.46 243.21,121.92 273.05,121.92 276.86,118.11 276.86,117.47 R63.1
BUS_FILE_READY
  Top 0.508: R135.1 30.48,65.41 32.38,63.5 R136.2 33.02,62.87 33.02,56.52 J2.V
BUS_INDEX_L
  Top 0.508: J2.Z 38.1,56.52 38.1,62.87 R138.2 37.47,63.5 35.56,65.41 R137.1 35.56,66.67 36.83,67.94 36.83,94.61 15.24,116.2 15.24,130.81 E11.1 15.88,132.72 22.23,139.06 E11.11
BUS_READ_GATE_L
  Top 0.508: R131.1 20.32,65.41 22.23,63.5 R132.2 22.86,62.87 22.86,56.52 J2.L
BUS_RESTORE_L  (via drill 0.61)
  Top 0.508: E22.5 48.26,16.51 48.26,19.68 C34.1 | R143.1 258.44,93.98 256.54,95.89 R144.2 256.54,97.16 256.54,103.5 J1.P | v93.98,30.48 105.41,41.91 105.41,66.04 123.83,84.45 v123.83,103.5
  Bottom 0.508: v93.98,30.48 60.96,30.48 54.61,24.13 51.44,24.13 48.26,20.95 C34.1 | v123.83,103.5 216.53,103.5 219.71,100.33 252.09,100.33 255.91,96.52 R144.2
BUS_RWS_READY_L
  Top 0.508: E12.5 289.56,8.89 290.83,10.16 290.83,97.16 288.29,99.69 288.29,112.39 282.57,118.11 271.78,118.11 271.78,117.47 R65.1 271.78,116.2 273.05,114.94 | 273.05,114.94 273.69,114.3 R66.2 | 273.05,114.94 273.05,106.05 274.32,104.78 J1.EE
BUS_SECTOR_ADDR_0L  (via drill 0.61)
  Top 0.508: E6.5 157.48,130.81 157.48,127.64 R17.1 157.48,126.36 v157.48,74.93 | R139.1 40.64,65.41 42.55,63.5 R140.2 43.18,62.87 43.18,56.52 J2.DD
  Bottom 0.508: v157.48,74.93 156.21,73.66 55.24,73.66 45.09,63.5 43.81,63.5 R140.2
BUS_SECTOR_ADDR_1L  (via drill 0.61)
  Top 0.508: R18.1 149.86,146.69 149.86,140.97 E6.13 149.86,138.43 151.13,137.16 v151.13,98.42 | R117.1 253.37,93.98 251.46,95.89 R118.2 251.46,97.16 251.46,103.5 J1.K
  Bottom 0.508: v151.13,98.42 155.57,93.98 183.51,93.98 184.78,95.25 249.56,95.25 250.82,96.52 R118.2
BUS_SECTOR_ADDR_2L  (via drill 0.61)
  Top 0.508: R16.1 154.94,144.15 154.94,140.97 E6.11 154.94,138.43 154.94,134.62 156.21,133.35 156.21,85.72 v142.88,72.39 | R55.1 50.16,43.18 48.26,45.09 R56.2 48.26,46.35 46.99,47.62 46.99,53.98 45.72,55.24 J2.FF
  Bottom 0.508: v142.88,72.39 69.22,72.39 55.24,58.42 48.9,58.42 46.35,55.88 J2.FF
BUS_SECTOR_ADDR_3L  (via drill 0.61)
  Top 0.508: E6.9 160.02,140.97 160.02,144.15 R11.1 160.02,145.41 158.75,146.69 158.75,150.5 158.12,151.13 153.67,151.13 153.67,128.91 154.94,127.64 154.94,86.36 v138.43,69.85 | R89.1 55.24,43.18 53.34,45.09 R90.2 53.34,46.35 53.34,50.16 52.07,51.44 52.07,53.98 50.8,55.24 J2.LL
  Bottom 0.508: v138.43,69.85 135.25,66.67 64.77,66.67 55.24,57.15 52.7,57.15 51.44,55.88 J2.LL
BUS_SECTOR_PULSE_L
  Top 0.508: R101.1 34.92,43.18 33.02,45.09 R102.2
  Bottom 0.508: J2.T 30.48,55.24 31.75,53.98 31.75,46.35 33.02,46.35 R102.2
BUS_SEEK_INCOMPLETE_L  (via drill 0.61)
  Top 0.508: E21.7 60.96,16.51 60.96,27.3 R27.1 60.96,28.57 66.04,33.66 v66.04,45.09 | R121.1 248.28,93.98 246.38,95.89 R122.2 246.38,97.16 246.38,103.5 J1.E | v208.28,46.99 210.82,49.53 210.82,53.34 212.09,54.61 212.09,57.15 217.17,62.23 v217.17,96.52
  Bottom 0.508: v66.04,45.09 67.94,46.99 v208.28,46.99 | v217.17,96.52 239.4,96.52 240.66,97.79 244.47,97.79 245.75,96.52 R122.2
BUS_STROBE_L
  Top 0.508: E22.3 45.72,8.89 57.15,20.32 57.15,38.73 60.96,42.55 R91.1 60.33,43.18 58.42,45.09 R92.2
  Bottom 0.508: J2.RR 55.88,55.24 57.15,53.98 57.15,46.35 58.42,46.35 R92.2
BUS_WP_SET_L
  Top 0.508: R105.1 24.77,43.18 22.86,45.09 R106.2
  Bottom 0.508: J2.J 20.32,55.24 21.59,53.98 21.59,46.35 22.86,46.35 R106.2
BUS_WP_STATUS_L
  Top 0.508: R133.1 25.4,65.41 27.3,63.5 R134.2 27.94,62.87 27.94,56.52 J2.R
BUS_WRITE_GATE_L
  Top 0.508: R57.1 45.09,43.18 43.18,45.09 R58.2 43.18,46.35 41.91,47.62 41.91,53.98 40.64,55.24 J2.BB 40.64,56.52 39.37,57.78 39.37,66.67 44.45,71.75 44.45,113.03 70.48,139.06 E9.13
CA_SW_1  (via drill 0.61)
  Top 0.508: E26.9 248.92,64.77 248.92,70.48 R45.2 248.92,71.75 v244.47,76.2 | v135.89,77.47 135.89,107.31 133.35,109.86 CYL1.3
  Bottom 0.508: v135.89,77.47 137.16,76.2 v244.47,76.2
CA_SW_2  (via drill 0.61)
  Top 0.508: E26.12 241.3,64.77 241.3,67.94 R44.2 241.3,69.22 241.3,80.01 v240.03,81.28 | v119.38,81.92 119.38,108.58 118.11,109.86 CYL2.3
  Bottom 0.508: v119.38,81.92 121.28,80.01 228.6,80.01 229.87,81.28 v240.03,81.28
CA_SW_4  (via drill 0.61)
  Top 0.508: E27.9 223.52,64.77 223.52,70.48 R43.2 223.52,71.75 223.52,78.11 v222.88,78.74 | v114.94,81.28 114.94,97.79 102.87,109.86 CYL4.3
  Bottom 0.508: v114.94,81.28 117.47,78.74 v222.88,78.74
CA_SW_8  (via drill 0.61)
  Top 0.508: E27.12 215.9,64.77 215.9,67.94 R42.2 215.9,69.22 215.9,90.81 v207.01,99.69 | v97.79,99.69 87.63,109.86 CYL8.3
  Bottom 0.508: v207.01,99.69 v97.79,99.69
CA_SW_16  (via drill 0.61)
  Top 0.508: E28.9 198.12,64.77 198.12,70.48 R41.2 198.12,71.75 198.12,83.19 v196.85,84.45 | v99.06,83.19 72.39,109.86 CYL16.3
  Bottom 0.508: v99.06,83.19 175.26,83.19 176.53,84.45 v196.85,84.45
CA_SW_32  (via drill 0.61)
  Top 0.508: E28.12 190.5,64.77 190.5,67.94 R40.2 | v159.38,109.86 165.1,104.14 v165.1,73.03
  Bottom 0.508: v159.38,109.86 143.51,109.86 140.97,112.39 58.42,112.39 57.15,111.12 CYL32.3 | v165.1,73.03 169.54,68.58 178.44,68.58 179.71,69.85 188.59,69.85 189.87,68.58 R40.2
CA_SW_64  (via drill 0.61)
  Top 0.508: E29.9 172.72,64.77 172.72,70.48 R39.2 172.72,71.75 172.72,104.14 v168.28,108.58
  Bottom 0.508: v168.28,108.58 160.02,116.84 141.6,116.84 140.97,116.2 60.96,116.2 57.15,112.39 43.18,112.39 41.91,111.12 CYL64.3
CA_SW_128  (via drill 0.61)
  Top 0.508: E29.12 165.1,64.77 165.1,67.94 R38.2 165.1,69.22 163.83,70.48 163.83,103.5 v158.75,108.58
  Bottom 0.508: v158.75,108.58 27.94,108.58 26.67,109.86 CYL128.3
CLOCK_H
  Top 0.508: E7.12 126.36,140.34 125.09,141.6 110.49,141.6 110.49,138.43 104.78,132.72 E8.5
  Bottom 0.508: E7.12 127.64,140.34 128.91,141.6 130.18,141.6 131.44,140.34 E7.10 | E8.1 94.61,131.44 95.89,130.18 102.23,130.18 103.5,131.44 E8.5
CONSTANT_WRITE_L  (via drill 0.61)
  Top 0.508: v159.38,125.73 175.26,109.86 175.26,88.27 176.53,87 CONSTANT_WRITE.2
  Bottom 0.508: v159.38,125.73 29.21,125.73 23.5,131.44 E11.4
DATA_BITS
  Bottom 0.508: BIT0.3 179.07,109.86 194.31,109.86 BIT1.3 196.85,109.86 212.09,109.86 BIT2.3 214.63,109.86 217.17,109.86 217.81,109.22 R7.1 219.07,109.22 229.24,109.22 229.87,109.86 BIT3.3
DC_ERASE  (via drill 0.61)
  Top 0.508: v101.6,120.02 90.17,131.44 90.17,132.08 83.82,138.43 E9.8 | v181.61,120.02 193.04,108.58 193.04,88.27 194.31,87 DC_ERASE.2
  Bottom 0.508: v181.61,120.02 v101.6,120.02
FWD_L  (via drill 0.61)
  Top 0.508: R36.1 71.12,79.38 71.12,81.92 FWD/REV.3 | v153.67,74.93 163.83,64.77 163.83,23.5 170.18,17.14 170.18,16.51 E17.9
  Bottom 0.508: E17.9 170.81,15.88 172.09,17.14 193.68,17.14 194.94,15.88 E16.9 | v153.67,74.93 120.02,74.93 114.94,80.01 74.3,80.01 72.39,81.92 FWD/REV.3
GND  (via drill 0.61)
  Top 0.508: E14.8 251.46,8.89 251.46,13.97 E14.9 251.46,16.51 251.46,26.04 254,28.57 254,29.84 C36.2 254,31.11 254,34.29 E30.4 | E16.7 198.75,7.62 205.1,7.62 C15.2 205.74,8.26 210.82,13.34 210.82,13.97 E15.13 211.46,14.61 212.72,14.61 E15.12 213.36,13.97 215.9,11.43 215.9,8.89 E15.4 216.53,6.99 217.81,6.99 E15.5 219.07,8.26 221.62,10.79 | E14.1 233.04,7.62 231.78,7.62 C14.2 230.5,7.62 224.16,7.62 E15.7 223.52,8.89 221.62,10.79 | E31.4 218.44,34.29 218.44,16.51 E15.10 219.07,14.61 220.34,14.61 E15.9 220.98,13.97 220.98,11.43 221.62,10.79 | C31.2 208.28,36.2 208.28,38.1 205.74,40.64 205.74,55.24 C27.2 205.74,56.52 v205.74,59.05 | v223.52,59.05 223.52,58.42 225.43,56.52 E27.7 | 172.72,10.79 157.48,10.79 154.94,8.26 C17.2 | 172.72,10.79 172.72,8.89 E17.7 | E29.7 175.26,54.61 175.26,45.72 173.99,44.45 173.99,38.1 175.26,36.83 E33.4 175.26,34.29 175.26,13.34 172.72,10.79 | D5.A 259.08,23.5 259.08,55.24 C25.2 | E12.7 294.64,8.89 294.64,11.43 292.1,13.97 E12.9 292.1,16.51 292.1,34.92 R23.1 292.1,36.2 294.64,38.73 294.64,54.61 E24.7 294.64,57.15 292.1,59.69 292.1,62.23 E24.9 | R31.1 276.86,51.44 276.86,55.24 C24.2 276.86,56.52 276.86,57.15 278.76,59.05 | 278.76,59.05 281.94,62.23 E24.13 | J1.F 245.75,106.68 244.47,106.68 J1.D | J1.J 249.56,106.68 250.82,106.68 J1.L 252.09,106.68 253.37,106.68 J1.N 254.63,106.68 255.91,106.68 J1.R | J1.R 257.18,106.68 258.44,106.68 J1.T 259.71,106.68 260.99,106.68 J1.V | J1.Z 266.06,106.68 264.8,106.68 J1.X | J1.FF 274.95,106.68 276.23,106.68 J1.JJ 276.86,106.05 275.59,104.78 275.59,86.36 | J1.NN 281.31,106.68 280.04,106.68 J1.LL
  Top 0.508: J1.TT 286.38,106.68 285.12,106.68 J1.RR | 255.27,124.46 254.63,124.46 R114.1 | 255.27,124.46 258.44,124.46 R72.1 | R70.1 264.8,124.46 268.61,124.46 R68.1 269.88,124.46 273.69,124.46 R66.1 274.32,125.09 274.32,131.44 C1.2 | R64.1 280.04,124.46 283.85,124.46 R78.1 285.12,124.46 288.93,124.46 R84.1 289.56,125.09 289.56,128.27 292.1,130.81 E1.7 | C2.2 248.92,131.44 248.92,125.09 R120.1 | 255.27,124.46 255.27,108.58 256.54,107.31 J1.R | R148.1 266.06,86.36 262.25,86.36 R146.1 | 275.59,86.36 272.42,86.36 R150.1 271.78,85.72 271.78,79.38 273.69,77.47 C44.- 273.69,74.93 273.69,72.39 C45.+ 274.95,69.85 274.95,62.87 278.76,59.05 | 275.59,86.36 276.23,86.36 R74.1 277.5,86.36 281.31,86.36 R76.1 | E19.10 119.38,13.97 119.38,10.16 118.11,8.89 118.11,6.35 118.75,5.71 121.28,5.71 121.28,6.99 E19.8 | E20.8 94.61,7.62 100.97,7.62 C19.2 | E21.4 66.67,7.62 73.03,7.62 C20.2 74.3,7.62 75.56,7.62 E20.1 76.2,8.89 76.2,11.43 78.74,13.97 E20.15 | E22.4 48.9,7.62 55.24,7.62 C21.2 | E23.7 31.11,7.62 37.47,7.62 C22.2 38.1,8.26 39.37,9.53 39.37,24.77 C68.- | FUNCTION.C1 114.94,36.2 114.3,35.56 114.3,27.94 106.68,20.32 106.68,16.51 E19.15 | R112.1 13.34,35.56 17.14,35.56 R108.1 18.41,35.56 22.23,35.56 R106.1 | R104.1 28.57,35.56 32.38,35.56 R102.1 33.02,36.2 31.75,37.47 31.75,53.34 | R100.1 38.73,35.56 42.55,35.56 R58.1 43.81,35.56 47.62,35.56 R56.1 48.26,34.92 48.26,28.57 C34.2 | C47.2 107.31,60.96 108.58,60.96 C48.2 109.86,60.96 111.12,60.96 C49.2 112.39,60.96 113.67,60.96 C50.2 | J2.E 18.41,53.34 19.68,53.34 J2.H 20.95,53.34 22.23,53.34 J2.K | J2.P 28.57,53.34 29.84,53.34 J2.S 31.11,53.34 31.75,53.34
  Top 0.508: 31.75,53.34 32.38,53.34 J2.U 33.66,53.34 34.92,53.34 J2.W 36.2,53.34 37.47,53.34 J2.Y 38.73,53.34 40.01,53.34 J2.AA | J2.EE 45.09,53.34 43.81,53.34 J2.CC | J2.MM 53.98,53.34 55.24,53.34 J2.PP 56.52,53.34 57.78,53.34 J2.SS 58.42,53.98 57.15,55.24 57.15,69.22 | R110.1 13.34,73.66 17.14,73.66 R130.1 18.41,73.66 22.23,73.66 R132.1 22.86,74.3 22.86,80.64 24.13,81.92 HEAD.3 | R136.1 32.38,73.66 28.57,73.66 R134.1 | R140.1 42.55,73.66 38.73,73.66 R138.1 | 57.15,69.22 53.34,73.03 R52.1 53.34,74.3 53.34,84.45 54.61,85.72 RTZ.2 57.15,85.72 69.85,85.72 FWD/REV.2 69.85,87 68.58,88.27 68.58,113.67 | 57.15,69.22 57.78,68.58 C53.2 | E4.7 213.36,130.81 213.36,130.18 215.9,127.64 R14.1 215.9,126.36 215.9,120.02 214.63,118.75 BIT2.1 | BIT1.1 195.58,118.75 195.58,131.44 C4.2 | E6.7 163.19,132.08 169.54,132.08 C5.2 | E5.2 175.9,131.44 177.16,131.44 E5.3 177.8,130.81 177.8,118.75 BIT0.1 | C61.- 167,97.79 167,113.03 C60.- | E9.2 71.75,131.44 73.03,131.44 E9.3 73.66,130.81 73.66,113.67 | E9.5 79.38,131.44 80.64,131.44 E9.6 81.92,131.44 83.19,131.44 E9.7 | 111.76,134.62 111.76,138.43 E8.9 | 111.76,134.62 111.76,133.35 E8.8 112.39,132.08 118.75,132.08 C7.2 | C10.2 37.47,132.08 31.11,132.08 E11.7 30.48,130.81 30.48,113.67 | 30.48,113.67 26.67,113.67 CYL128.2 | 30.48,113.67 39.37,113.67 CYL64.2 | 68.58,113.67 57.15,113.67 CYL32.2 | 68.58,113.67 69.85,113.67 CYL16.2 72.39,113.67 73.66,113.67 | 73.66,113.67 85.09,113.67 CYL8.2 | 107.95,113.67 102.87,113.67 CYL4.2 | 107.95,113.67 115.57,113.67 CYL2.2 | 129.54,112.39 129.54,91.44 131.44,89.53 POWER.B | 129.54,112.39 130.81,113.67 CYL1.2
  Top 0.508: 129.54,112.39 129.54,123.19 137.16,130.81 E7.7 | 111.76,134.62 107.95,134.62 107.95,113.67
  Bottom 0.508: E14.8 252.09,7.62 258.44,7.62 C13.2 259.08,6.99 260.35,5.71 267.33,5.71 268.61,6.99 E13.4 269.88,7.62 276.23,7.62 C12.2 276.86,6.99 278.13,5.71 292.74,5.71 294,6.99 E12.7 | 233.04,32.38 234.31,33.66 235.59,33.66 SECTOR.11 | 233.04,32.38 SECTOR.12 233.04,32.38 | C30.2 243.21,35.56 241.94,34.29 236.22,34.29 SECTOR.11 | E30.4 253.37,34.92 252.09,33.66 236.22,33.66 SECTOR.11 | 233.04,32.38 230.5,34.92 219.07,34.92 E31.4 217.81,34.92 216.53,33.66 209.55,33.66 208.28,34.92 C31.2 207.65,35.56 201.29,35.56 E32.4 200.03,34.92 198.75,33.66 191.77,33.66 190.5,34.92 C32.2 189.87,35.56 175.9,35.56 E33.4 | E27.7 226.69,55.88 233.04,55.88 C26.2 | E28.7 201.29,55.88 205.1,55.88 C27.2 | v205.74,59.05 v223.52,59.05 | E18.7 147.96,7.62 154.31,7.62 C17.2 | E17.7 173.35,7.62 179.71,7.62 C16.2 | E29.7 175.9,55.88 182.25,55.88 C28.2 | E26.7 252.09,55.88 258.44,55.88 C25.2 259.08,56.52 260.35,57.78 274.32,57.78 276.23,55.88 C24.2 | E24.9 291.46,62.87 290.19,62.87 E24.10 288.93,64.14 287.65,65.41 286.38,65.41 285.12,64.14 E24.12 283.85,62.87 282.57,62.87 E24.13 | C38.2 286.38,45.72 281.31,50.8 277.5,50.8 R31.1 | J1.B 241.94,106.68 243.21,106.68 J1.D | J1.J 248.28,106.68 247.01,106.68 J1.F | J1.X 263.52,106.68 262.25,106.68 J1.V | J1.Z 267.33,106.68 268.61,106.68 J1.BB 269.88,106.68 271.14,106.68 J1.DD 272.42,106.68 273.69,106.68 J1.FF | J1.LL 278.76,106.68 277.5,106.68 J1.JJ | J1.RR 283.85,106.68 282.57,106.68 J1.NN | E2.7 267.33,132.08 273.69,132.08 C1.2 | C2.2 248.28,132.08 241.94,132.08 E3.8 240.66,132.72 239.4,133.99 222.25,133.99 220.98,132.72 C3.2 220.34,132.08 214,132.08 E4.7
  Bottom 0.508: R124.1 244.47,124.46 248.28,124.46 R120.1 249.56,124.46 253.37,124.46 R114.1 | R70.1 263.52,124.46 259.71,124.46 R72.1 | R64.1 278.76,124.46 274.95,124.46 R66.1 | CONSTANT_WRITE.3 179.07,81.92 194.31,81.92 DC_ERASE.3 196.85,83.19 201.93,83.19 202.56,83.82 R15.1 203.84,83.82 210.19,83.82 212.09,85.72 WRITE_BUTTON.2 214.63,86.36 240.66,86.36 R126.1 241.94,86.36 245.75,86.36 R122.1 247.01,86.36 250.82,86.36 R118.1 252.09,86.36 255.91,86.36 R144.1 257.18,86.36 260.99,86.36 R146.1 | R150.1 271.14,86.36 267.33,86.36 R148.1 | R76.1 282.57,86.36 286.38,86.36 R80.1 287.65,86.36 291.46,86.36 R82.1 | C18.2 128.91,7.62 122.56,7.62 E19.8 121.28,8.26 120.02,9.53 102.87,9.53 101.6,8.26 C19.2 | E20.8 93.34,8.26 92.08,9.53 78.11,9.53 76.83,8.26 E20.1 | C23.2 12.7,6.99 13.97,5.71 28.57,5.71 29.84,6.99 E23.7 | E22.4 47.62,8.26 46.35,9.53 39.37,9.53 38.1,8.26 C22.2 | R104.1 27.3,35.56 23.5,35.56 R106.1 | R100.1 37.47,35.56 33.66,35.56 R102.1 | R56.1 48.9,35.56 52.7,35.56 R90.1 53.98,35.56 57.78,35.56 R92.1 58.42,34.92 75.56,34.92 76.83,36.2 DRIVE.C1 77.47,36.83 80.01,36.83 81.92,34.92 113.67,34.92 114.94,36.2 FUNCTION.C1 | C68.- 41.91,26.04 43.81,27.94 47.62,27.94 C34.2 | E21.4 65.41,8.26 64.14,9.53 57.15,9.53 55.88,8.26 C21.2 | C47.2 106.05,60.96 104.14,60.96 102.23,59.05 C52.- 100.97,59.05 99.69,60.33 68.58,60.33 61.59,53.34 J2.UU 60.33,53.34 59.05,53.34 J2.SS | C29.2 156.84,55.88 154.94,57.78 148.59,57.78 C67.- 146.05,59.05 144.15,60.96 114.94,60.96 C50.2 | J2.C 15.88,53.34 17.14,53.34 J2.E | J2.K 23.5,53.34 24.77,53.34 J2.M 26.04,53.34 27.3,53.34 J2.P
  Bottom 0.508: J2.CC 42.55,53.34 41.27,53.34 J2.AA | J2.EE 46.35,53.34 47.62,53.34 J2.HH 48.9,53.34 50.16,53.34 J2.KK 51.44,53.34 52.7,53.34 J2.MM | C53.2 59.05,68.58 62.87,68.58 C51.2 | R134.1 27.3,73.66 23.5,73.66 R132.1 | R138.1 37.47,73.66 33.66,73.66 R136.1 | R140.1 43.81,73.66 47.62,73.66 R88.1 48.9,73.66 52.7,73.66 R52.1 | BIT3.1 229.87,118.11 214.63,118.11 BIT2.1 212.09,117.47 196.85,117.47 BIT1.1 | C4.2 194.94,132.08 188.59,132.08 E5.7 187.32,131.44 186.06,130.18 173.35,130.18 | BIT0.1 176.53,117.47 173.99,114.94 168.91,114.94 C60.- | 173.35,130.18 171.45,130.18 170.18,131.44 C5.2 | 173.35,130.18 174.62,131.44 E5.2 | E10.7 56.52,132.08 65.41,132.08 C9.2 66.04,131.44 67.31,130.18 75.56,130.18 | C8.2 90.81,132.08 84.45,132.08 E9.7 | 75.56,130.18 74.3,131.44 E9.3 | 75.56,130.18 76.83,130.18 78.11,131.44 E9.5 | E7.7 137.79,132.08 144.15,132.08 C6.2 145.41,132.08 146.69,132.08 E6.1 147.96,131.44 149.22,130.18 160.66,130.18 161.93,131.44 E6.7 | C11.2 12.7,131.44 12.7,114.94 24.13,114.94 CYL128.2 | CYL32.2 54.61,113.67 41.91,113.67 CYL64.2 | CYL4.2 100.33,113.67 87.63,113.67 CYL8.2 | CYL1.2 130.81,113.67 118.11,113.67 CYL2.2
HEAD_SELECT_L
  Top 0.508: R100.2 38.1,45.09 40.01,43.18 R99.1 | HEAD.2 26.67,85.72 34.29,78.11 34.29,57.78 35.56,56.52 J2.X
  Bottom 0.508: J2.X 35.56,55.24 36.83,53.98 36.83,46.35 38.1,46.35 R100.2
N$1
  Top 0.508: E13.1 261.62,6.35 261.62,4.45 262.89,3.17 291.46,3.17 291.46,6.99 E12.6
N$2
  Top 0.508: E7.6 134.62,133.35 133.35,134.62 133.35,141.6 123.83,151.13 81.28,151.13 81.28,140.97 E9.9
N$3
  Top 0.508: E11.13 18.41,139.06 19.68,139.06 E11.12
  Bottom 0.508: 45.09,137.79 43.81,139.06 E10.13 | 45.09,137.79 53.98,137.79 55.24,139.06 E10.8 | 45.09,137.79 22.23,137.79 20.95,139.06 E11.12
N$4
  Top 0.508: E10.11 48.9,139.06 50.16,139.06 E10.10
N$5  (via drill 0.61)
  Top 0.508: E2.4 259.08,133.35 261.62,135.89 261.62,138.43 E2.10 261.62,140.97 261.62,144.15 R10.1 | v186.69,143.51 183.51,140.34 E5.10
  Bottom 0.508: v186.69,143.51 259.71,143.51 260.99,144.78 R10.1
N$6
  Top 0.508: E7.4 129.54,133.35 129.54,138.43 E7.11
N$7  (via drill 0.61)
  Top 0.508: v143.51,130.18 137.16,136.53 137.16,138.43 E7.8
  Bottom 0.508: v143.51,130.18 133.99,130.18 132.72,131.44 E7.5
N$8
  Top 0.508: E11.3 20.95,132.72 27.3,139.06 E11.9
N$9  (via drill 0.61)
  Top 0.508: v143.51,123.19 143.51,128.27 135.89,135.89 135.89,137.16 134.62,138.43 E7.9 | v210.82,123.19 212.09,124.46 212.09,137.16 213.36,138.43 E4.8
  Bottom 0.508: v143.51,123.19 v210.82,123.19
N$10
  Top 0.508: R20.1 261.62,28.57 261.62,29.84 C36.1 | E13.3 266.7,8.89 265.43,10.16 265.43,29.21 Q1.E
  Bottom 0.508: R20.1 262.25,27.94 263.52,29.21 264.16,29.21 Q1.E
N$11
  Top 0.508: E8.14 99.06,140.97 99.06,144.15 C63.2
N$12
  Top 0.508: E8.6 106.68,130.81 106.68,127.64 C62.2
N$13
  Top 0.508: E8.15 96.52,140.97 96.52,146.69 R9.E 97.79,147.32 100.33,149.86 R9.S 102.23,149.22 102.23,148.59 106.05,144.78 C63.1
N$14
  Top 0.508: R8.1 116.2,127 114.94,127 C62.1 113.67,127 113.67,127.64 109.86,131.44 E8.7
N$15  (via drill 0.61)
  Top 0.508: v76.83,128.91 74.93,130.81 74.93,137.16 73.66,138.43 E9.12
  Bottom 0.508: v76.83,128.91 123.83,128.91 126.36,131.44 E7.3
N$16
  Top 0.508: Q1.B1 267.33,27.94 271.14,27.94 R21.1
N$17
  Top 0.508: Q1.B2 266.7,31.11 266.7,34.92 R22.2
N$18
  Top 0.508: 279.4,35.56 281.31,35.56 R23.2 | 279.4,35.56 277.5,35.56 R22.1 | E12.13 281.94,16.51 279.4,19.05 279.4,19.68 C37.2 279.4,20.95 279.4,35.56
N$19  (via drill 0.61)
  Top 0.508: E14.2 236.85,8.26 242.57,13.97 242.57,17.14 245.11,19.68 245.11,20.95 245.75,21.59 v247.65,21.59 248.92,21.59 248.92,16.51 E14.10 | v146.69,4.45 151.13,8.89 v151.13,18.41 | E12.12 284.48,16.51 287.02,19.05 287.02,19.68 C37.1
  Bottom 0.508: v146.69,4.45 43.81,4.45 41.27,6.99 E22.1 | v151.13,18.41 169.54,18.41 170.81,19.68 233.68,19.68 235.59,21.59 v247.65,21.59 285.12,21.59 286.38,20.32 C37.1
N$20
  Top 0.508: E17.1 158.12,8.26 159.38,9.53 170.18,9.53 170.18,8.89 E17.6
N$21  (via drill 0.61)
  Top 0.508: v59.69,36.83 59.69,10.16 58.42,8.89 E21.1 | v147.32,45.72 152.4,40.64 152.4,5.08 156.21,1.27 161.93,1.27 161.93,6.99 E17.3 163.19,6.99 164.47,6.99 E17.4
  Bottom 0.508: v59.69,36.83 68.58,45.72 v147.32,45.72
N$22
  Top 0.508: E14.15 236.22,16.51 236.22,19.68 C35.1 236.22,20.95 236.22,22.23 R25.1
N$23
  Top 0.508: E14.14 239.4,15.88 243.21,19.68 243.21,20.32 C35.2
N$24
  Top 0.508: E14.7 248.92,6.35 248.92,3.17 R28.1 249.56,2.54 252.73,5.71 252.73,18.41 254,19.68 C33.1
N$25
  Top 0.508: E14.6 246.38,8.89 245.11,10.16 245.11,18.41 246.38,19.68 C33.2
N$26  (via drill 0.61)
  Top 0.508: v85.09,17.14 85.09,10.16 83.82,8.89 E20.4 | v111.12,20.95 111.76,20.32 111.76,16.51 E19.13
  Bottom 0.508: v85.09,17.14 88.9,20.95 v111.12,20.95
N$27  (via drill 0.61)
  Top 0.508: v87.63,17.14 87.63,10.16 86.36,8.89 E20.5 | v114.3,19.68 114.3,16.51 E19.12
  Bottom 0.508: v87.63,17.14 90.17,19.68 v114.3,19.68
N$28  (via drill 0.61)
  Top 0.508: v125.09,23.5 125.09,4.45 112.39,4.45 110.49,6.35 110.49,9.53 112.39,9.53 113.67,8.26 E19.5 | v189.23,26.04 196.85,18.41 196.85,10.16 195.58,8.89 E16.6
  Bottom 0.508: v125.09,23.5 127.64,26.04 v189.23,26.04
N$29  (via drill 0.61)
  Top 0.508: v168.28,144.78 168.28,141.6 160.02,133.35 E6.6 | v219.71,146.05 225.43,140.34 E3.15
  Bottom 0.508: v168.28,144.78 169.54,146.05 v219.71,146.05
N$30
  Bottom 0.508: RUN.2 41.91,87 42.55,87.63 52.7,87.63 54.61,89.53 RTZ.1
N$31  (via drill 0.61)
  Top 0.508: v152.4,144.15 152.4,140.97 E6.12 | v219.71,148.59 227.97,140.34 E3.14
  Bottom 0.508: v152.4,144.15 155.57,147.32 191.77,147.32 193.04,148.59 v219.71,148.59
N$32  (via drill 0.61)
  Top 0.508: v157.48,149.86 157.48,140.97 E6.10 | v224.79,147.32 231.14,140.97 E3.13
  Bottom 0.508: v157.48,149.86 222.25,149.86 v224.79,147.32
N$33
  Top 0.508: E6.8 162.56,140.97 165.74,144.15 165.74,149.86 167,151.13 233.68,151.13 233.68,140.97 E3.12
N$34
  Bottom 0.508: E6.2 150.5,131.44 151.76,131.44 E6.3
N$35  (via drill 0.61)
  Top 0.508: v115.57,19.68 115.57,5.71 113.67,5.71 112.39,6.99 E19.4 | v193.68,24.77 198.12,20.32 198.12,16.51 E16.8
  Bottom 0.508: v115.57,19.68 118.11,22.23 162.56,22.23 165.1,24.77 v193.68,24.77
N$36
  Top 0.508: E10.1 41.27,131.44 42.55,131.44 E10.2 | E10.4 48.9,131.44 50.16,131.44 E10.5
  Bottom 0.508: 52.7,133.99 153.03,133.99 154.31,132.72 E6.4 | 52.7,133.99 51.44,132.72 E10.5 | 52.7,133.99 45.09,133.99 43.81,132.72 E10.2
N$37
  Top 0.508: R1.1 101.6,81.92 101.6,85.72 ADDR_INV.A
N$38
  Top 0.508: R2.1 116.84,81.92 116.84,85.72 SEEK_INC.A
N$39
  Top 0.508: R3.1 132.08,81.92 132.08,85.72 POWER.A
N$40  (via drill 0.61)
  Top 0.508: v116.84,18.41 116.84,16.51 E19.11 | v165.74,23.5 172.72,16.51 E17.8
  Bottom 0.508: E20.11 89.53,15.88 92.08,18.41 v116.84,18.41 118.11,19.68 161.93,19.68 v165.74,23.5
N$41  (via drill 0.61)
  Top 0.508: v182.25,28.57 182.25,22.23 187.96,16.51 E16.12 | v111.76,23.5 109.22,20.95 109.22,16.51 E19.14
  Bottom 0.508: E20.14 81.92,14.61 83.19,13.34 107.31,13.34 108.58,14.61 E19.14 | v182.25,28.57 125.09,28.57 120.02,23.5 v111.76,23.5
N$42
  Top 0.508: E25.2 264.16,54.61 264.16,46.35 266.06,44.45 276.23,44.45 276.23,45.72 R29.1 277.5,45.72 278.76,45.72 C38.1
N$43  (via drill 0.61)
  Top 0.508: v260.35,42.55 260.35,27.3 260.99,26.67 260.99,21.59 259.71,20.32 R32.1 | E25.6 266.7,62.23 265.43,60.96 265.43,47.62 266.7,46.35 R29.2
  Bottom 0.508: v260.35,42.55 263.52,45.72 266.06,45.72 R29.2 267.33,45.72 269.88,48.26 276.23,48.26 R30.2
N$44
  Top 0.508: R30.1 266.7,48.9 266.7,50.16 R31.2 266.7,51.44 266.7,54.61 E25.3
N$46
  Bottom 0.508: 208.91,9.53 210.19,8.26 E15.2 | 208.91,9.53 207.65,10.79 20.95,10.79 18.41,8.26 E23.2 | 208.91,9.53 280.04,9.53 281.31,8.26 E12.2
N$47
  Top 0.508: E15.1 208.91,8.26 210.19,9.53 214.63,9.53 214.63,6.35 219.71,1.27 240.66,1.27 240.66,6.99 E14.4
N$48
  Bottom 0.508: D3.A 54.61,22.86 57.15,25.4 62.23,25.4 D2.C
N$53
  Bottom 0.508: D4.A 54.61,20.32 57.15,22.86 62.23,22.86 D3.C
N$55
  Top 0.508: E13.6 267.33,14.61 276.23,5.71 283.21,5.71 283.21,8.89 283.85,9.53 287.02,9.53 287.02,8.89 E12.4
N$57  (via drill 0.61)
  Top 0.508: v243.84,12.06 243.84,13.97 E14.12 | v264.16,12.06 264.16,13.97 E13.7 | v132.72,12.06 136.53,8.26 E18.3
  Bottom 0.508: v264.16,12.06 v243.84,12.06 v132.72,12.06 19.68,12.06 15.88,8.26 E23.1
N$58
  Top 0.508: 269.24,17.78 269.24,19.68 R32.2 269.24,20.95 269.24,22.23 D5.C | 269.24,17.78 269.24,16.51 E13.5 | 269.24,17.78 278.76,8.26 E12.1
N$59
  Top 0.508: E16.11 190.5,13.97 190.5,11.43 187.96,8.89 E16.3 187.96,6.35 187.96,5.71 211.46,5.71 212.72,6.99 E15.3
N$60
